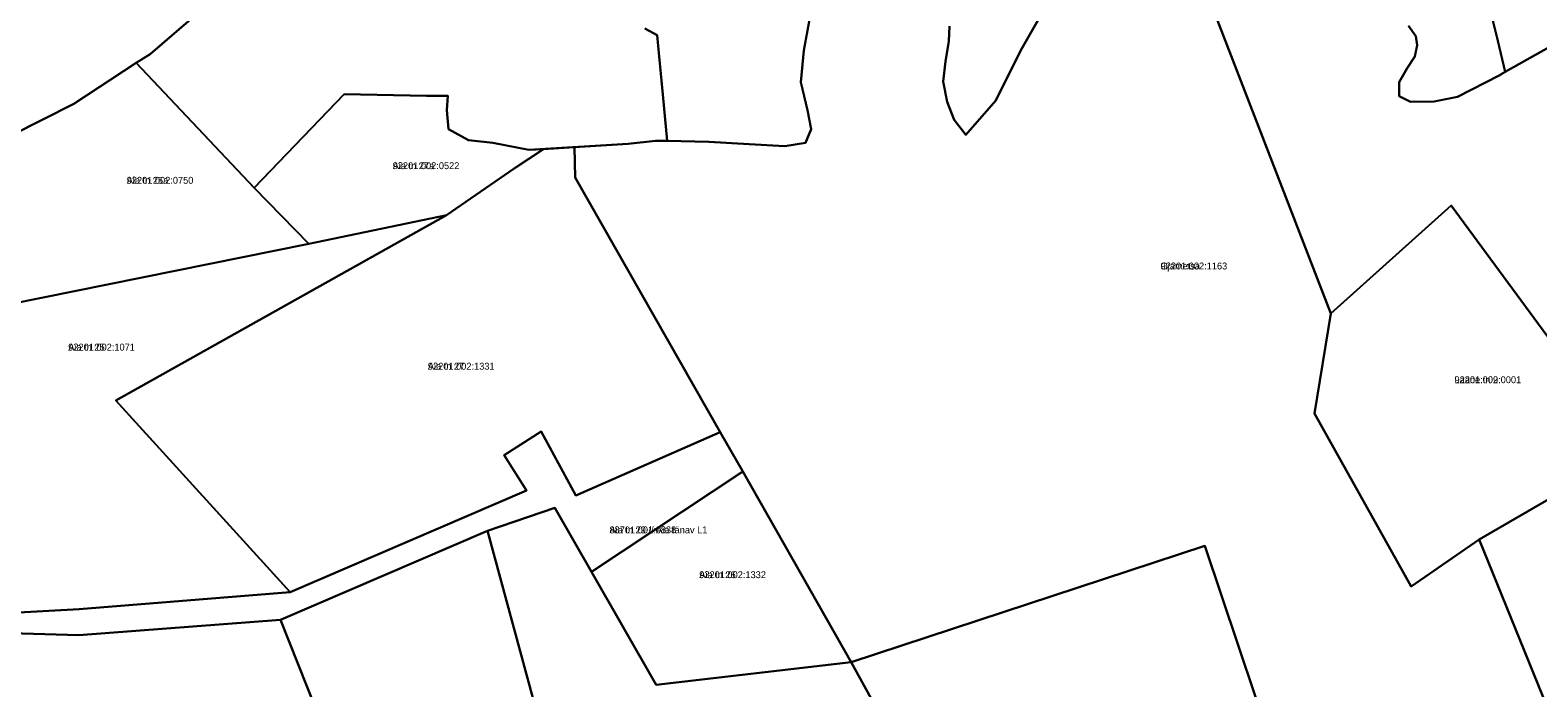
# Model space of a CAD drawing. Extents: x 601493 to 643081, y 6584980 to 6634019.
# Drawn here: x 610425.7 to 610753.7, y 6605427.7 to 6605570.9 of the extents above; entities that cross this region are included whole.
import ezdxf

# ---------------------------------------------------------------- set-up
doc = ezdxf.new("R2010")
doc.units = 0
for name, color, linetype in [('L_AADRESS', 7, 'Continuous'), ('PIIR', 7, 'Continuous'), ('TUNNUS', 7, 'Continuous')]:
    doc.layers.add(name, color=color, linetype=linetype)

msp = doc.modelspace()

# ---------------------------------------------------------------- linework, layer by layer
at = {"layer": 'PIIR'}
for points in [[(610736.95, 6605601.41), (610727.06, 6605631.76), (610721.77, 6605654.74), (610713.75, 6605683.91), (610736.92, 6605690.82), (610743.83, 6605660.73), (610758.89, 6605592.68), (610761.75, 6605580.09), (610761.33, 6605574.93), (610759.58, 6605570.71), (610756.17, 6605567.2), (610746.6, 6605561.79), (610745, 6605568.53)], [(610425.55, 6605578.59), (610437.08, 6605592.92), (610444.82, 6605602.51), (610459.02, 6605620.13), (610481.55, 6605603.61), (610493.38, 6605601), (610476.79, 6605587.15), (610473.64, 6605584.61), (610451.8, 6605565.68), (610448.69, 6605563.75), (610435.15, 6605554.82), (610421.65, 6605548.04), (610419.3, 6605547.36), (610404.58, 6605543.12), (610393.75, 6605545.93), (610399.96, 6605555.08)], [(610419.45, 6605543.94), (610419.3, 6605547.36), (610421.65, 6605548.04), (610435.15, 6605554.82), (610448.69, 6605563.75), (610474.41, 6605536.59), (610486.26, 6605524.34), (610420.96, 6605511.15)], [(610414.59, 6605464.21), (610392.09, 6605472.66), (610398.82, 6605488.75), (610405.83, 6605504.94), (610412.44, 6605519.07), (610392.2, 6605536.79), (610377.39, 6605549.01), (610383.24, 6605558.65), (610399.96, 6605555.08), (610393.75, 6605545.93), (610404.58, 6605543.12), (610419.3, 6605547.36), (610419.45, 6605543.94), (610420.96, 6605511.15), (610486.26, 6605524.34), (610516.24, 6605530.61), (610444.31, 6605490.25), (610482.23, 6605448.56), (610436.34, 6605444.88), (610413.82, 6605443.63)], [(610493.97, 6605556.93), (610511.91, 6605556.57), (610516.52, 6605556.59), (610516.3, 6605553.46), (610516.71, 6605549.34), (610521.04, 6605546.97), (610526.3, 6605546.35), (610534.16, 6605544.81), (610537.34, 6605544.99), (610530.94, 6605540.74), (610516.24, 6605530.61), (610486.26, 6605524.34), (610474.41, 6605536.59)], [(610444.31, 6605490.25), (610516.24, 6605530.61), (610530.94, 6605540.74), (610537.34, 6605544.99), (610544.07, 6605545.42), (610544.27, 6605538.84), (610575.81, 6605483.42), (610544.4, 6605469.62), (610536.85, 6605483.54), (610528.78, 6605478.36), (610533.67, 6605470.67), (610482.23, 6605448.56)], [(610708.65, 6605509.22), (610734.86, 6605532.72), (610757.66, 6605501.65), (610766.06, 6605474.64), (610740.89, 6605460.03), (610726.14, 6605449.82), (610705.06, 6605487.47)], [(610365.08, 6605442.74), (610363.1, 6605449.26), (610369.91, 6605448.17), (610374.55, 6605445.54), (610390.95, 6605445.31), (610413.82, 6605443.63), (610436.34, 6605444.88), (610482.23, 6605448.56), (610533.67, 6605470.67), (610528.78, 6605478.36), (610536.85, 6605483.54), (610544.4, 6605469.62), (610575.81, 6605483.42), (610580.7, 6605474.82), (610547.79, 6605453.01), (610539.84, 6605466.91), (610525.13, 6605461.9), (610480.16, 6605442.56), (610436.24, 6605439.2), (610372.2, 6605441.12)], [(610547.79, 6605453.01), (610580.7, 6605474.82), (610604.3, 6605433.35), (610561.87, 6605428.42)], [(610556.58, 6605363.11), (610524.85, 6605419.69), (610535.27, 6605424.74), (610525.13, 6605461.9), (610539.84, 6605466.91), (610547.79, 6605453.01), (610561.87, 6605428.42), (610604.3, 6605433.35), (610628.84, 6605388.68), (610579.06, 6605368.46), (610558.85, 6605368.75)], [(610480.16, 6605442.56), (610525.13, 6605461.9), (610535.27, 6605424.74), (610524.85, 6605419.69), (610556.58, 6605363.11), (610553.97, 6605356.6), (610579.64, 6605354.1), (610579.06, 6605368.46), (610628.84, 6605388.68), (610697.48, 6605237.12), (610552.14, 6605261.1)], [(610699.43, 6605404.37), (610628.84, 6605388.68), (610604.3, 6605433.35), (610681.21, 6605458.68)], [(610416.39, 6605307.74), (610415.41, 6605310.5), (610414.05, 6605314.35), (610410.84, 6605323.43), (610398.59, 6605359.7), (610383.2, 6605405.34), (610372.2, 6605441.12), (610436.24, 6605439.2), (610480.16, 6605442.56), (610552.14, 6605261.1), (610499.49, 6605267.13), (610495.66, 6605267.57), (610500.46, 6605245.8), (610496.03, 6605246.32), (610438.06, 6605252.8)]]:
    msp.add_lwpolyline(points, close=True, dxfattribs=at)
for points in [[(610736.95, 6605601.41), (610745, 6605568.53), (610746.6, 6605561.79), (610745.24, 6605561.02), (610736.17, 6605556.38), (610731.11, 6605555.35), (610725.96, 6605555.25), (610723.48, 6605556.49), (610723.48, 6605559.58), (610725.24, 6605562.57), (610726.89, 6605565.14), (610727.41, 6605567.62), (610727.17, 6605569.54), (610725.52, 6605571.8)], [(610559.38, 6605571.25), (610562.09, 6605569.82), (610562.46, 6605565.84), (610563.33, 6605556.9), (610564.26, 6605546.76), (610561.69, 6605546.81), (610555.76, 6605546.14), (610534.16, 6605544.81), (610526.3, 6605546.35), (610521.04, 6605546.97), (610516.71, 6605549.34), (610516.3, 6605553.46), (610516.52, 6605556.59), (610511.91, 6605556.57), (610493.97, 6605556.93), (610474.41, 6605536.59), (610448.69, 6605563.75), (610451.8, 6605565.68), (610473.64, 6605584.61)], [(610757.66, 6605501.65), (610734.86, 6605532.72), (610708.65, 6605509.22), (610679.24, 6605585.22)], [(610679.24, 6605585.22), (610708.65, 6605509.22), (610705.06, 6605487.47), (610726.14, 6605449.82), (610740.89, 6605460.03), (610799.13, 6605316.51)], [(610699.43, 6605404.37), (610681.21, 6605458.68), (610604.3, 6605433.35), (610580.7, 6605474.82), (610575.81, 6605483.42), (610544.27, 6605538.84), (610544.07, 6605545.42), (610555.76, 6605546.14), (610561.69, 6605546.81), (610564.26, 6605546.76), (610573.35, 6605546.58), (610582.11, 6605546.07), (610589.84, 6605545.65), (610594.38, 6605546.38), (610595.62, 6605549.36), (610594.8, 6605553.49), (610593.36, 6605559.57), (610593.98, 6605566.48), (610595.22, 6605573.18)], [(610595.22, 6605573.18), (610593.98, 6605566.48), (610593.36, 6605559.57), (610594.8, 6605553.49), (610595.62, 6605549.36), (610594.38, 6605546.38), (610589.84, 6605545.65), (610582.11, 6605546.07), (610573.35, 6605546.58), (610564.26, 6605546.76), (610563.33, 6605556.9), (610562.09, 6605569.82), (610559.38, 6605571.25)], [(610625.67, 6605571.77), (610625.57, 6605568.47), (610624.84, 6605564.04), (610624.32, 6605559.71), (610625.15, 6605555.27), (610626.69, 6605551.36), (610629.27, 6605548.06), (610635.77, 6605555.58), (610641.1, 6605566.37), (610644.87, 6605572.95)], [(610644.87, 6605572.95), (610641.1, 6605566.37), (610635.77, 6605555.58), (610629.27, 6605548.06), (610626.69, 6605551.36), (610625.15, 6605555.27), (610624.32, 6605559.71), (610624.84, 6605564.04), (610625.57, 6605568.47), (610625.67, 6605571.77)], [(610725.52, 6605571.8), (610727.17, 6605569.54), (610727.41, 6605567.62), (610726.89, 6605565.14), (610725.24, 6605562.57), (610723.48, 6605559.58), (610723.48, 6605556.49), (610725.96, 6605555.25), (610731.11, 6605555.35), (610736.17, 6605556.38), (610745.24, 6605561.02), (610746.6, 6605561.79), (610756.17, 6605567.2)], [(610799.13, 6605316.51), (610740.89, 6605460.03), (610766.06, 6605474.64)]]:
    msp.add_lwpolyline(points, dxfattribs=at)

# ---------------------------------------------------------------- texts
at = {"layer": 'L_AADRESS'}
for s, p in [('Aia tn 27a', (610504.54, 6605540.63)), ('Aia tn 25a', (610446.67, 6605537.45)), ('Ojametsa', (610671.6, 6605518.8)), ('Aia tn 25', (610433.95, 6605501.14)), ('Aia tn 27', (610512.2, 6605496.99)), ('Lääne tn 9', (610735.56, 6605494.05)), ('Aia tn 29 // Aia tänav L1', (610551.71, 6605461.37)), ('Aia tn 26', (610571.24, 6605451.62))]:
    msp.add_text(s, height=1.5, dxfattribs=at).set_placement(p)
at = {"layer": 'TUNNUS'}
for s, p in [('92201:002:0522', (610504.54, 6605540.63)), ('92201:002:0750', (610446.67, 6605537.45)), ('92201:002:1163', (610671.6, 6605518.8)), ('92201:002:1071', (610433.95, 6605501.14)), ('92201:002:1331', (610512.2, 6605496.99)), ('92201:002:0001', (610735.56, 6605494.05)), ('88701:001:0838', (610551.71, 6605461.37)), ('92201:002:1332', (610571.24, 6605451.62))]:
    msp.add_text(s, height=1.5, dxfattribs=at).set_placement(p)

doc.saveas('drawing.dxf')
